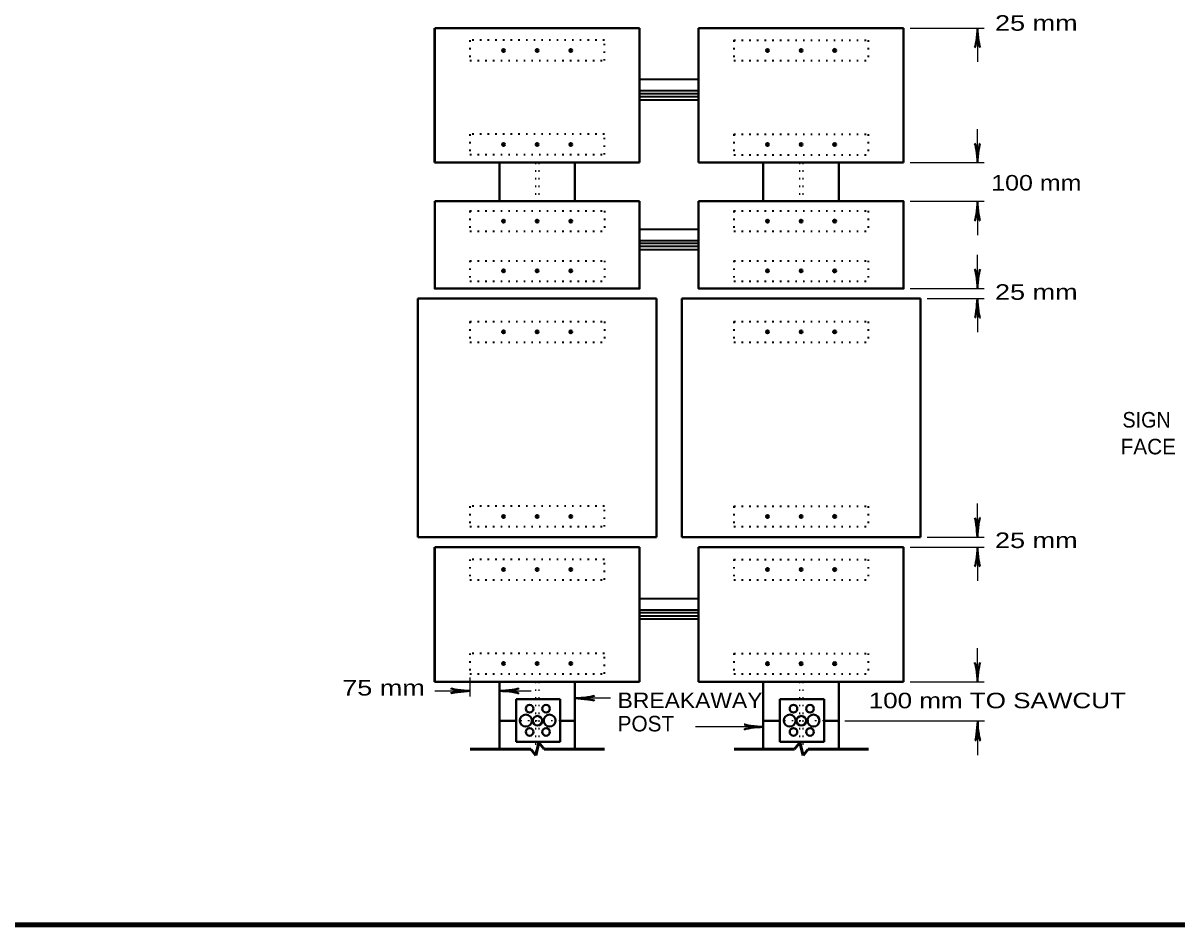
# Model space of a CAD drawing. Extents: x 851 to 1706, y -23 to 521.
# Drawn here: x 1133.3 to 1358.6, y -11.8 to 164.2 of the extents above; entities that cross this region are included whole.
import ezdxf
from ezdxf.enums import TextEntityAlignment as Align

# ---------------------------------------------------------------- set-up
doc = ezdxf.new("R2010")
doc.units = 0
doc.linetypes.add('DOTTED', pattern=[1.5, 0.3, -1.2])
doc.layers.add('1', color=7, linetype='Continuous', lineweight=35)

msp = doc.modelspace()

# ---------------------------------------------------------------- hatches: boundary and pattern name
at = {"layer": '1'}
for points in [[(1227.43, 158.896, 1), (1226.859, 158.896, 1)], [(1233.991, 158.896, 1), (1233.42, 158.896, 1)], [(1240.552, 158.896, 1), (1239.981, 158.896, 1)], [(1278.961, 158.896, 1), (1278.39, 158.896, 1)], [(1285.522, 158.896, 1), (1284.951, 158.896, 1)], [(1292.083, 158.896, 1), (1291.512, 158.896, 1)], [(1227.43, 140.538, 1), (1226.859, 140.538, 1)], [(1233.991, 140.538, 1), (1233.42, 140.538, 1)], [(1240.552, 140.538, 1), (1239.981, 140.538, 1)], [(1278.961, 140.525, 1), (1278.39, 140.525, 1)], [(1285.522, 140.525, 1), (1284.951, 140.525, 1)], [(1292.083, 140.525, 1), (1291.512, 140.525, 1)], [(1227.43, 125.571, 1), (1226.859, 125.571, 1)], [(1233.991, 125.571, 1), (1233.42, 125.571, 1)], [(1240.552, 125.571, 1), (1239.981, 125.571, 1)], [(1278.961, 125.571, 1), (1278.39, 125.571, 1)], [(1285.522, 125.571, 1), (1284.951, 125.571, 1)], [(1292.083, 125.571, 1), (1291.512, 125.571, 1)], [(1227.43, 115.839, 1), (1226.859, 115.839, 1)], [(1233.991, 115.839, 1), (1233.42, 115.839, 1)], [(1240.552, 115.839, 1), (1239.981, 115.839, 1)], [(1278.961, 115.839, 1), (1278.39, 115.839, 1)], [(1285.522, 115.839, 1), (1284.951, 115.839, 1)], [(1292.083, 115.839, 1), (1291.512, 115.839, 1)], [(1227.43, 103.947, 1), (1226.859, 103.947, 1)], [(1233.991, 103.947, 1), (1233.42, 103.947, 1)], [(1240.552, 103.947, 1), (1239.981, 103.947, 1)], [(1278.961, 103.947, 1), (1278.39, 103.947, 1)], [(1285.522, 103.947, 1), (1284.951, 103.947, 1)], [(1292.083, 103.947, 1), (1291.512, 103.947, 1)], [(1227.43, 67.916, 1), (1226.859, 67.916, 1)], [(1233.991, 67.916, 1), (1233.42, 67.916, 1)], [(1240.552, 67.916, 1), (1239.981, 67.916, 1)], [(1278.961, 67.916, 1), (1278.39, 67.916, 1)], [(1285.522, 67.916, 1), (1284.951, 67.916, 1)], [(1292.083, 67.916, 1), (1291.512, 67.916, 1)], [(1227.43, 57.528, 1), (1226.859, 57.528, 1)], [(1233.991, 57.528, 1), (1233.42, 57.528, 1)], [(1240.552, 57.528, 1), (1239.981, 57.528, 1)], [(1278.961, 57.528, 1), (1278.39, 57.528, 1)], [(1285.522, 57.528, 1), (1284.951, 57.528, 1)], [(1292.083, 57.528, 1), (1291.512, 57.528, 1)], [(1227.43, 39.171, 1), (1226.859, 39.171, 1)], [(1233.991, 39.171, 1), (1233.42, 39.171, 1)], [(1240.552, 39.171, 1), (1239.981, 39.171, 1)], [(1278.961, 39.157, 1), (1278.39, 39.157, 1)], [(1285.522, 39.157, 1), (1284.951, 39.157, 1)], [(1292.083, 39.157, 1), (1291.512, 39.157, 1)]]:
    msp.add_hatch(color=256, dxfattribs=at).paths.add_polyline_path(points)

# ---------------------------------------------------------------- linework, layer by layer
at = {"layer": '1', "lineweight": 40}
for p, q in [((1213.694, 136.998), (1213.694, 163.242)), ((1213.695, 163.242), (1253.717, 163.242)), ((1213.695, 136.998), (1213.695, 163.242)), ((1253.716, 163.242), (1253.716, 136.998)), ((1253.717, 163.242), (1253.717, 136.998)), ((1265.226, 163.242), (1265.226, 136.998)), ((1305.248, 163.242), (1265.226, 163.242)), ((1265.226, 163.242), (1265.226, 136.998)), ((1305.248, 136.998), (1305.248, 163.242)), ((1305.248, 136.998), (1305.248, 163.242)), ((1213.694, 136.998), (1253.716, 136.998)), ((1213.695, 136.998), (1253.717, 136.998)), ((1226.324, 136.998), (1226.324, 129.453)), ((1241.087, 136.998), (1241.087, 129.453)), ((1305.248, 136.998), (1265.226, 136.998)), ((1305.248, 136.998), (1265.226, 136.998)), ((1277.855, 136.998), (1277.855, 129.453)), ((1292.618, 136.998), (1292.618, 129.453)), ((1253.717, 129.453), (1213.695, 129.453)), ((1210.414, 110.426), (1256.997, 110.426)), ((1210.414, 110.426), (1210.414, 63.843)), ((1256.997, 110.426), (1256.997, 63.843)), ((1308.528, 110.426), (1261.945, 110.426)), ((1261.945, 110.426), (1261.945, 63.843)), ((1308.528, 110.426), (1308.528, 63.843)), ((1210.414, 63.843), (1256.997, 63.843)), ((1308.528, 63.843), (1261.945, 63.843)), ((1213.694, 35.631), (1213.694, 61.875)), ((1213.695, 61.875), (1253.717, 61.875)), ((1213.695, 35.631), (1213.695, 61.875)), ((1253.716, 61.875), (1253.716, 35.631)), ((1253.717, 61.875), (1253.717, 35.631)), ((1265.226, 61.875), (1265.226, 35.631)), ((1265.226, 61.875), (1265.226, 35.631)), ((1305.248, 61.875), (1265.226, 61.875)), ((1265.226, 61.875), (1265.226, 35.631)), ((1305.248, 35.631), (1305.248, 61.875)), ((1305.248, 35.631), (1305.248, 61.875)), ((1213.694, 35.631), (1253.716, 35.631)), ((1213.695, 35.631), (1253.717, 35.631)), ((1226.324, 35.631), (1226.324, 22.509)), ((1241.087, 35.631), (1241.087, 22.509)), ((1305.248, 35.631), (1265.226, 35.631)), ((1305.248, 35.631), (1265.226, 35.631)), ((1277.855, 35.631), (1277.855, 22.509)), ((1292.618, 35.631), (1292.618, 22.509)), ((1238.216, 32.241), (1229.577, 32.241)), ((1229.577, 32.241), (1229.577, 23.876)), ((1238.216, 32.241), (1238.216, 23.876)), ((1289.72, 32.241), (1281.081, 32.241)), ((1281.081, 32.241), (1281.081, 23.876)), ((1289.72, 32.241), (1289.72, 23.876)), ((1229.577, 28.031), (1226.379, 28.031)), ((1238.216, 28.031), (1241.141, 28.031)), ((1281.081, 28.031), (1277.91, 28.031)), ((1289.72, 28.031), (1292.672, 28.031)), ((1238.216, 23.876), (1229.577, 23.876)), ((1289.72, 23.876), (1281.081, 23.876))]:
    msp.add_line(p, q, dxfattribs=at)
at = {"layer": '1', "lineweight": 25}
for p, q in [((1306.56, 163.242), (1320.994, 163.242)), ((1319.682, 163.242), (1319.682, 156.681)), ((1319.682, 136.971), (1319.682, 143.532)), ((1306.56, 136.998), (1320.994, 136.998)), ((1306.56, 129.453), (1320.994, 129.453)), ((1319.682, 129.389), (1319.682, 122.828)), ((1319.682, 112.395), (1319.682, 118.956)), ((1306.56, 112.395), (1320.994, 112.395)), ((1309.84, 110.426), (1320.994, 110.426)), ((1319.682, 110.426), (1319.682, 103.865)), ((1319.682, 63.843), (1319.682, 70.404)), ((1309.84, 63.843), (1320.994, 63.843)), ((1306.56, 61.875), (1320.994, 61.875)), ((1319.682, 61.875), (1319.682, 55.314)), ((1319.682, 35.604), (1319.682, 42.165)), ((1220.583, 36.452), (1220.583, 32.72)), ((1213.749, 33.855), (1220.638, 33.855)), ((1226.379, 33.855), (1232.557, 33.855)), ((1306.56, 35.631), (1320.994, 35.631)), ((1248.003, 32.405), (1241.141, 32.405)), ((1293.766, 28.031), (1321.049, 28.031)), ((1319.736, 21.306), (1319.736, 27.867)), ((1277.91, 26.801), (1264.595, 26.801))]:
    msp.add_line(p, q, dxfattribs=at)
at = {"layer": '1', "linetype": 'DOTTED'}
for p, q in [((1272.115, 160.891), (1298.359, 160.891)), ((1272.115, 160.891), (1272.115, 156.9)), ((1298.359, 160.891), (1298.359, 156.9)), ((1272.115, 156.9), (1298.359, 156.9)), ((1272.115, 142.52), (1298.359, 142.52)), ((1272.115, 142.52), (1272.115, 138.529)), ((1298.359, 142.52), (1298.359, 138.529)), ((1272.115, 138.529), (1298.359, 138.529)), ((1220.583, 127.567), (1246.828, 127.567)), ((1220.583, 127.567), (1220.583, 123.576)), ((1246.828, 127.567), (1246.828, 123.576)), ((1272.115, 127.567), (1298.359, 127.567)), ((1272.115, 127.567), (1272.115, 123.576)), ((1298.359, 127.567), (1298.359, 123.576)), ((1220.583, 123.576), (1246.828, 123.576)), ((1272.115, 123.576), (1298.359, 123.576)), ((1220.583, 117.835), (1246.828, 117.835)), ((1220.583, 117.835), (1220.583, 113.843)), ((1246.828, 117.835), (1246.828, 113.843)), ((1272.115, 117.835), (1298.359, 117.835)), ((1272.115, 117.835), (1272.115, 113.843)), ((1298.359, 117.835), (1298.359, 113.843)), ((1220.583, 113.843), (1246.828, 113.843)), ((1272.115, 113.843), (1298.359, 113.843)), ((1220.583, 105.943), (1246.828, 105.943)), ((1220.583, 105.943), (1220.583, 101.952)), ((1246.828, 105.943), (1246.828, 101.952)), ((1272.115, 105.943), (1298.359, 105.943)), ((1272.115, 105.943), (1272.115, 101.952)), ((1298.359, 105.943), (1298.359, 101.952)), ((1220.583, 101.952), (1246.828, 101.952)), ((1272.115, 101.952), (1298.359, 101.952)), ((1272.115, 69.912), (1298.359, 69.912)), ((1272.115, 69.912), (1272.115, 65.921)), ((1298.359, 69.912), (1298.359, 65.921)), ((1272.115, 65.921), (1298.359, 65.921)), ((1272.115, 59.524), (1298.359, 59.524)), ((1272.115, 59.524), (1272.115, 55.533)), ((1298.359, 59.524), (1298.359, 55.533)), ((1272.115, 55.533), (1298.359, 55.533)), ((1272.115, 41.153), (1298.359, 41.153)), ((1272.115, 41.153), (1272.115, 37.162)), ((1298.359, 41.153), (1298.359, 37.162)), ((1272.115, 37.162), (1298.359, 37.162))]:
    msp.add_line(p, q, dxfattribs=at)
at = {"layer": '1', "linetype": 'DOTTED', "lineweight": 25}
for p, q in [((1298.359, 160.891), (1298.359, 156.9)), ((1298.359, 142.52), (1298.359, 138.557)), ((1298.359, 142.52), (1298.359, 138.529)), ((1233.377, 136.998), (1233.377, 129.453)), ((1234.033, 136.998), (1234.033, 129.453)), ((1284.909, 136.998), (1284.909, 129.453)), ((1285.565, 136.998), (1285.565, 129.453)), ((1298.359, 127.567), (1298.359, 123.576)), ((1298.359, 69.912), (1298.359, 65.921)), ((1298.359, 59.524), (1298.359, 55.533)), ((1298.359, 41.153), (1298.359, 37.189)), ((1298.359, 41.153), (1298.359, 37.162)), ((1233.377, 35.631), (1233.377, 21.169)), ((1234.033, 35.631), (1234.033, 23.739)), ((1284.909, 35.631), (1284.909, 23.739)), ((1285.565, 35.631), (1285.565, 21.169)), ((1238.216, 28.031), (1229.577, 28.031)), ((1289.72, 28.031), (1281.081, 28.031))]:
    msp.add_line(p, q, dxfattribs=at)
at = {"layer": '1'}
for p, q in [((1253.717, 153.264), (1265.226, 153.264)), ((1253.717, 151.05), (1265.226, 151.05)), ((1265.226, 150.448), (1253.717, 150.448)), ((1265.226, 149.82), (1253.717, 149.82)), ((1253.717, 149.273), (1265.226, 149.273)), ((1253.717, 124.013), (1265.226, 124.013)), ((1253.717, 121.799), (1265.226, 121.799)), ((1265.226, 121.197), (1253.717, 121.197)), ((1265.226, 120.596), (1253.717, 120.596)), ((1253.717, 120.022), (1265.226, 120.022)), ((1253.717, 51.897), (1265.226, 51.897)), ((1253.717, 49.682), (1265.226, 49.682)), ((1265.226, 49.081), (1253.717, 49.081)), ((1265.226, 48.452), (1253.717, 48.452)), ((1253.717, 47.905), (1265.226, 47.905))]:
    msp.add_line(p, q, dxfattribs=at)
at = {"layer": '1', "lineweight": 53}
for p, q in [((1234.033, 23.739), (1233.432, 21.224)), ((1234.033, 23.739), (1235.072, 22.454)), ((1284.991, 23.739), (1283.979, 22.454)), ((1284.991, 23.739), (1285.619, 21.224)), ((1232.448, 22.454), (1220.638, 22.454)), ((1232.448, 22.454), (1233.432, 21.224)), ((1246.882, 22.454), (1235.072, 22.454)), ((1272.169, 22.454), (1283.979, 22.454)), ((1286.603, 22.454), (1285.619, 21.224)), ((1286.603, 22.454), (1298.413, 22.454))]:
    msp.add_line(p, q, dxfattribs=at)
at = {"layer": '1', "lineweight": 158}
msp.add_line((1699.744, -11.848), (908.144, -11.848), dxfattribs=at)
at = {"layer": '1', "linetype": 'DOTTED'}
for points in [[(1246.828, 160.891), (1220.583, 160.891), (1220.583, 156.9), (1246.828, 156.9)], [(1246.828, 142.52), (1220.583, 142.52), (1220.583, 138.557), (1246.828, 138.557)], [(1246.828, 69.912), (1220.583, 69.912), (1220.583, 65.921), (1246.828, 65.921)], [(1246.828, 59.524), (1220.583, 59.524), (1220.583, 55.533), (1246.828, 55.533)], [(1246.828, 41.153), (1220.583, 41.153), (1220.583, 37.189), (1246.828, 37.189)]]:
    msp.add_lwpolyline(points, close=True, dxfattribs=at)
at = {"layer": '1', "lineweight": 40}
msp.add_lwpolyline([(1213.695, 129.453), (1213.695, 112.395), (1253.717, 112.395), (1253.717, 129.453)], dxfattribs=at)
msp.add_lwpolyline([(1265.226, 129.453), (1305.248, 129.453), (1305.248, 112.395), (1265.226, 112.395)], close=True, dxfattribs=at)
for centre, radius in [((1227.145, 158.896), 0.286), ((1233.706, 158.896), 0.286), ((1240.266, 158.896), 0.286), ((1278.676, 158.896), 0.286), ((1285.237, 158.896), 0.286), ((1291.798, 158.896), 0.286), ((1227.145, 140.538), 0.286), ((1233.706, 140.538), 0.286), ((1240.266, 140.538), 0.286), ((1278.676, 140.525), 0.286), ((1285.237, 140.525), 0.286), ((1291.798, 140.525), 0.286), ((1227.145, 125.571), 0.286), ((1233.706, 125.571), 0.286), ((1240.266, 125.571), 0.286), ((1278.676, 125.571), 0.286), ((1285.237, 125.571), 0.286), ((1291.798, 125.571), 0.286), ((1227.145, 115.839), 0.286), ((1233.706, 115.839), 0.286), ((1240.266, 115.839), 0.286), ((1278.676, 115.839), 0.286), ((1285.237, 115.839), 0.286), ((1291.798, 115.839), 0.286), ((1227.145, 103.947), 0.286), ((1233.706, 103.947), 0.286), ((1240.266, 103.947), 0.286), ((1278.676, 103.947), 0.286), ((1285.237, 103.947), 0.286), ((1291.798, 103.947), 0.286), ((1227.145, 67.916), 0.286), ((1233.706, 67.916), 0.286), ((1240.266, 67.916), 0.286), ((1278.676, 67.916), 0.286), ((1285.237, 67.916), 0.286), ((1291.798, 67.916), 0.286), ((1227.145, 57.528), 0.286), ((1233.706, 57.528), 0.286), ((1240.266, 57.528), 0.286), ((1278.676, 57.528), 0.286), ((1285.237, 57.528), 0.286), ((1291.798, 57.528), 0.286), ((1227.145, 39.171), 0.286), ((1233.706, 39.171), 0.286), ((1240.266, 39.171), 0.286), ((1278.676, 39.157), 0.286), ((1285.237, 39.157), 0.286), ((1291.798, 39.157), 0.286), ((1232.236, 30.371), 0.745), ((1235.459, 30.371), 0.745), ((1283.756, 30.371), 0.745), ((1286.979, 30.371), 0.745), ((1231.493, 28.049), 1.17), ((1233.765, 28.021), 0.927), ((1236.13, 28.049), 1.17), ((1283.013, 28.049), 1.17), ((1285.285, 28.021), 0.927), ((1287.65, 28.049), 1.17), ((1232.236, 25.833), 0.745), ((1235.459, 25.833), 0.745), ((1283.756, 25.833), 0.745), ((1286.979, 25.833), 0.745)]:
    msp.add_circle(centre, radius, dxfattribs=at)
for centre, major_axis, ratio, start_param, end_param in [((1319.307, 161.816), (0.205, 2.343), 0.122415, 3.1415927, 5.386832), ((1319.307, 161.816), (0.205, 2.343), 0.122415, 3.1415927, 5.386832), ((1319.947, 161.778), (-0.23, 2.305), 0.07063, 0.8650754, 3.1424706), ((1319.947, 161.778), (-0.23, 2.305), 0.07063, 0.8650754, 3.1424706), ((1319.307, 138.392), (0.205, -2.343), 0.122415, 0.8963533, 3.1415927), ((1319.947, 138.431), (-0.23, -2.305), 0.07063, 3.1407148, 5.41811), ((1319.307, 127.968), (0.205, 2.343), 0.122415, 3.1415927, 5.386832), ((1319.947, 127.929), (-0.23, 2.305), 0.07063, 0.8650754, 3.1424706), ((1319.307, 113.832), (0.205, -2.343), 0.122415, 0.8963533, 3.1415927), ((1319.307, 113.832), (0.205, -2.343), 0.122415, 0.8963533, 3.1415927), ((1319.947, 113.871), (-0.23, -2.305), 0.07063, 3.1407148, 5.41811), ((1319.947, 113.871), (-0.23, -2.305), 0.07063, 3.1407148, 5.41811), ((1319.392, 108.962), (0.23, 2.305), 0.07063, 3.1407148, 5.41811), ((1319.392, 108.962), (0.23, 2.305), 0.07063, 3.1407148, 5.41811), ((1320.032, 109), (-0.205, 2.343), 0.122415, 0.8963533, 3.1415927), ((1320.032, 109), (-0.205, 2.343), 0.122415, 0.8963533, 3.1415927), ((1319.392, 65.319), (0.23, -2.305), 0.07063, 0.8650754, 3.1424706), ((1319.392, 65.319), (0.23, -2.305), 0.07063, 0.8650754, 3.1424706), ((1320.032, 65.281), (-0.205, -2.343), 0.122415, 3.1415927, 5.386832), ((1320.032, 65.281), (-0.205, -2.343), 0.122415, 3.1415927, 5.386832), ((1319.307, 60.449), (0.205, 2.343), 0.122415, 3.1415927, 5.386832), ((1319.307, 60.449), (0.205, 2.343), 0.122415, 3.1415927, 5.386832), ((1319.947, 60.411), (-0.23, 2.305), 0.07063, 0.8650754, 3.1424706), ((1319.947, 60.411), (-0.23, 2.305), 0.07063, 0.8650754, 3.1424706), ((1319.307, 37.025), (0.205, -2.343), 0.122415, 0.8963533, 3.1415927), ((1319.947, 37.063), (-0.23, -2.305), 0.07063, 3.1407148, 5.41811), ((1219.203, 34.204), (2.343, -0.205), 0.122415, 3.1415927, 5.386832), ((1219.203, 34.204), (2.343, -0.205), 0.122415, 3.1415927, 5.386832), ((1219.164, 33.564), (2.305, 0.23), 0.07063, 0.8650754, 3.1424706), ((1219.164, 33.564), (2.305, 0.23), 0.07063, 0.8650754, 3.1424706), ((1227.807, 33.479), (-2.343, 0.205), 0.122415, 3.1415927, 5.386832), ((1227.846, 34.119), (-2.305, -0.23), 0.07063, 0.8650754, 3.1424706), ((1242.569, 32.766), (-2.343, -0.205), 0.122415, 0.8963533, 3.1415927), ((1242.569, 32.766), (-2.343, -0.205), 0.122415, 0.8963533, 3.1415927), ((1242.608, 32.126), (-2.305, 0.23), 0.07063, 3.1407148, 5.41811), ((1242.608, 32.126), (-2.305, 0.23), 0.07063, 3.1407148, 5.41811), ((1276.427, 27.084), (2.305, -0.23), 0.07063, 3.1407148, 5.41811), ((1319.446, 26.407), (0.23, 2.305), 0.07063, 3.1407148, 5.41811), ((1320.087, 26.446), (-0.205, 2.343), 0.122415, 0.8963533, 3.1415927), ((1276.466, 26.444), (2.343, 0.205), 0.122415, 0.8963533, 3.1415927)]:
    msp.add_ellipse(centre, major_axis=major_axis, ratio=ratio, start_param=start_param, end_param=end_param, dxfattribs=at)

# ---------------------------------------------------------------- texts
at = {"layer": '1'}
for s, width, p in [('25 mm', 1.3, (1331.165, 162.735)), ('100 mm', 1.2, (1331.165, 131.531)), ('25 mm', 1.3, (1331.165, 110.201)), ('SIGN', 0.95, (1352.698, 85.257)), ('25 mm', 1.3, (1331.165, 61.733)), ('75 mm', 1.3, (1203.706, 32.941)), ('100 mm TO SAWCUT', 1.25, (1323.543, 30.449))]:
    msp.add_text(s, height=3.037, dxfattribs=dict(at, width=width)).set_placement(p, align=Align.CENTER)
msp.add_text('FACE', height=3.037, dxfattribs=at).set_placement((1353.034, 80.024), align=Align.CENTER)
at = {"layer": '1', "width": 1.1}
msp.add_text('BREAKAWAY ', height=3.037, dxfattribs=at).set_placement((1249.405, 30.488))
at = {"layer": '1'}
msp.add_text('POST', height=3.037, dxfattribs=at).set_placement((1249.405, 25.932))

doc.saveas('drawing.dxf')
